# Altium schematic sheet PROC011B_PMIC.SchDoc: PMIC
size 431 x 279 mm; Date: Not shown in title block; ApprovedBy: Not shown in title block; CheckedBy: Not shown in title block; Author: Not shown in title block; CompanyName: Not shown in title block; Engineer: Not shown in title block; Organization: Not shown in title block; Address1: Not shown in title block; Address2: Not shown in title block; Address3: Not shown in title block; Address4: Not shown in title block; DocumentNumber: 1; Revision: Use project parameter SCH_Rev; SheetNumber: 8; SheetTotal: 17; PageSetup: Record=PageOptions¦CenterHorizontal=True¦CenterVertical=True¦PrintScale=1.00¦XCorrection=1.00¦YCorrection=1.00¦PrintKind=0¦BorderSize=5000000¦LeftOffset=0¦BottomOffset=0¦Orientation=2¦PaperLength=1000¦PaperWidth=1000¦Scale=100¦PaperSource=15¦PrintQuality=600¦MediaType=1¦DitherType=10¦PaperKind=Letter¦PrintScaleMode=1
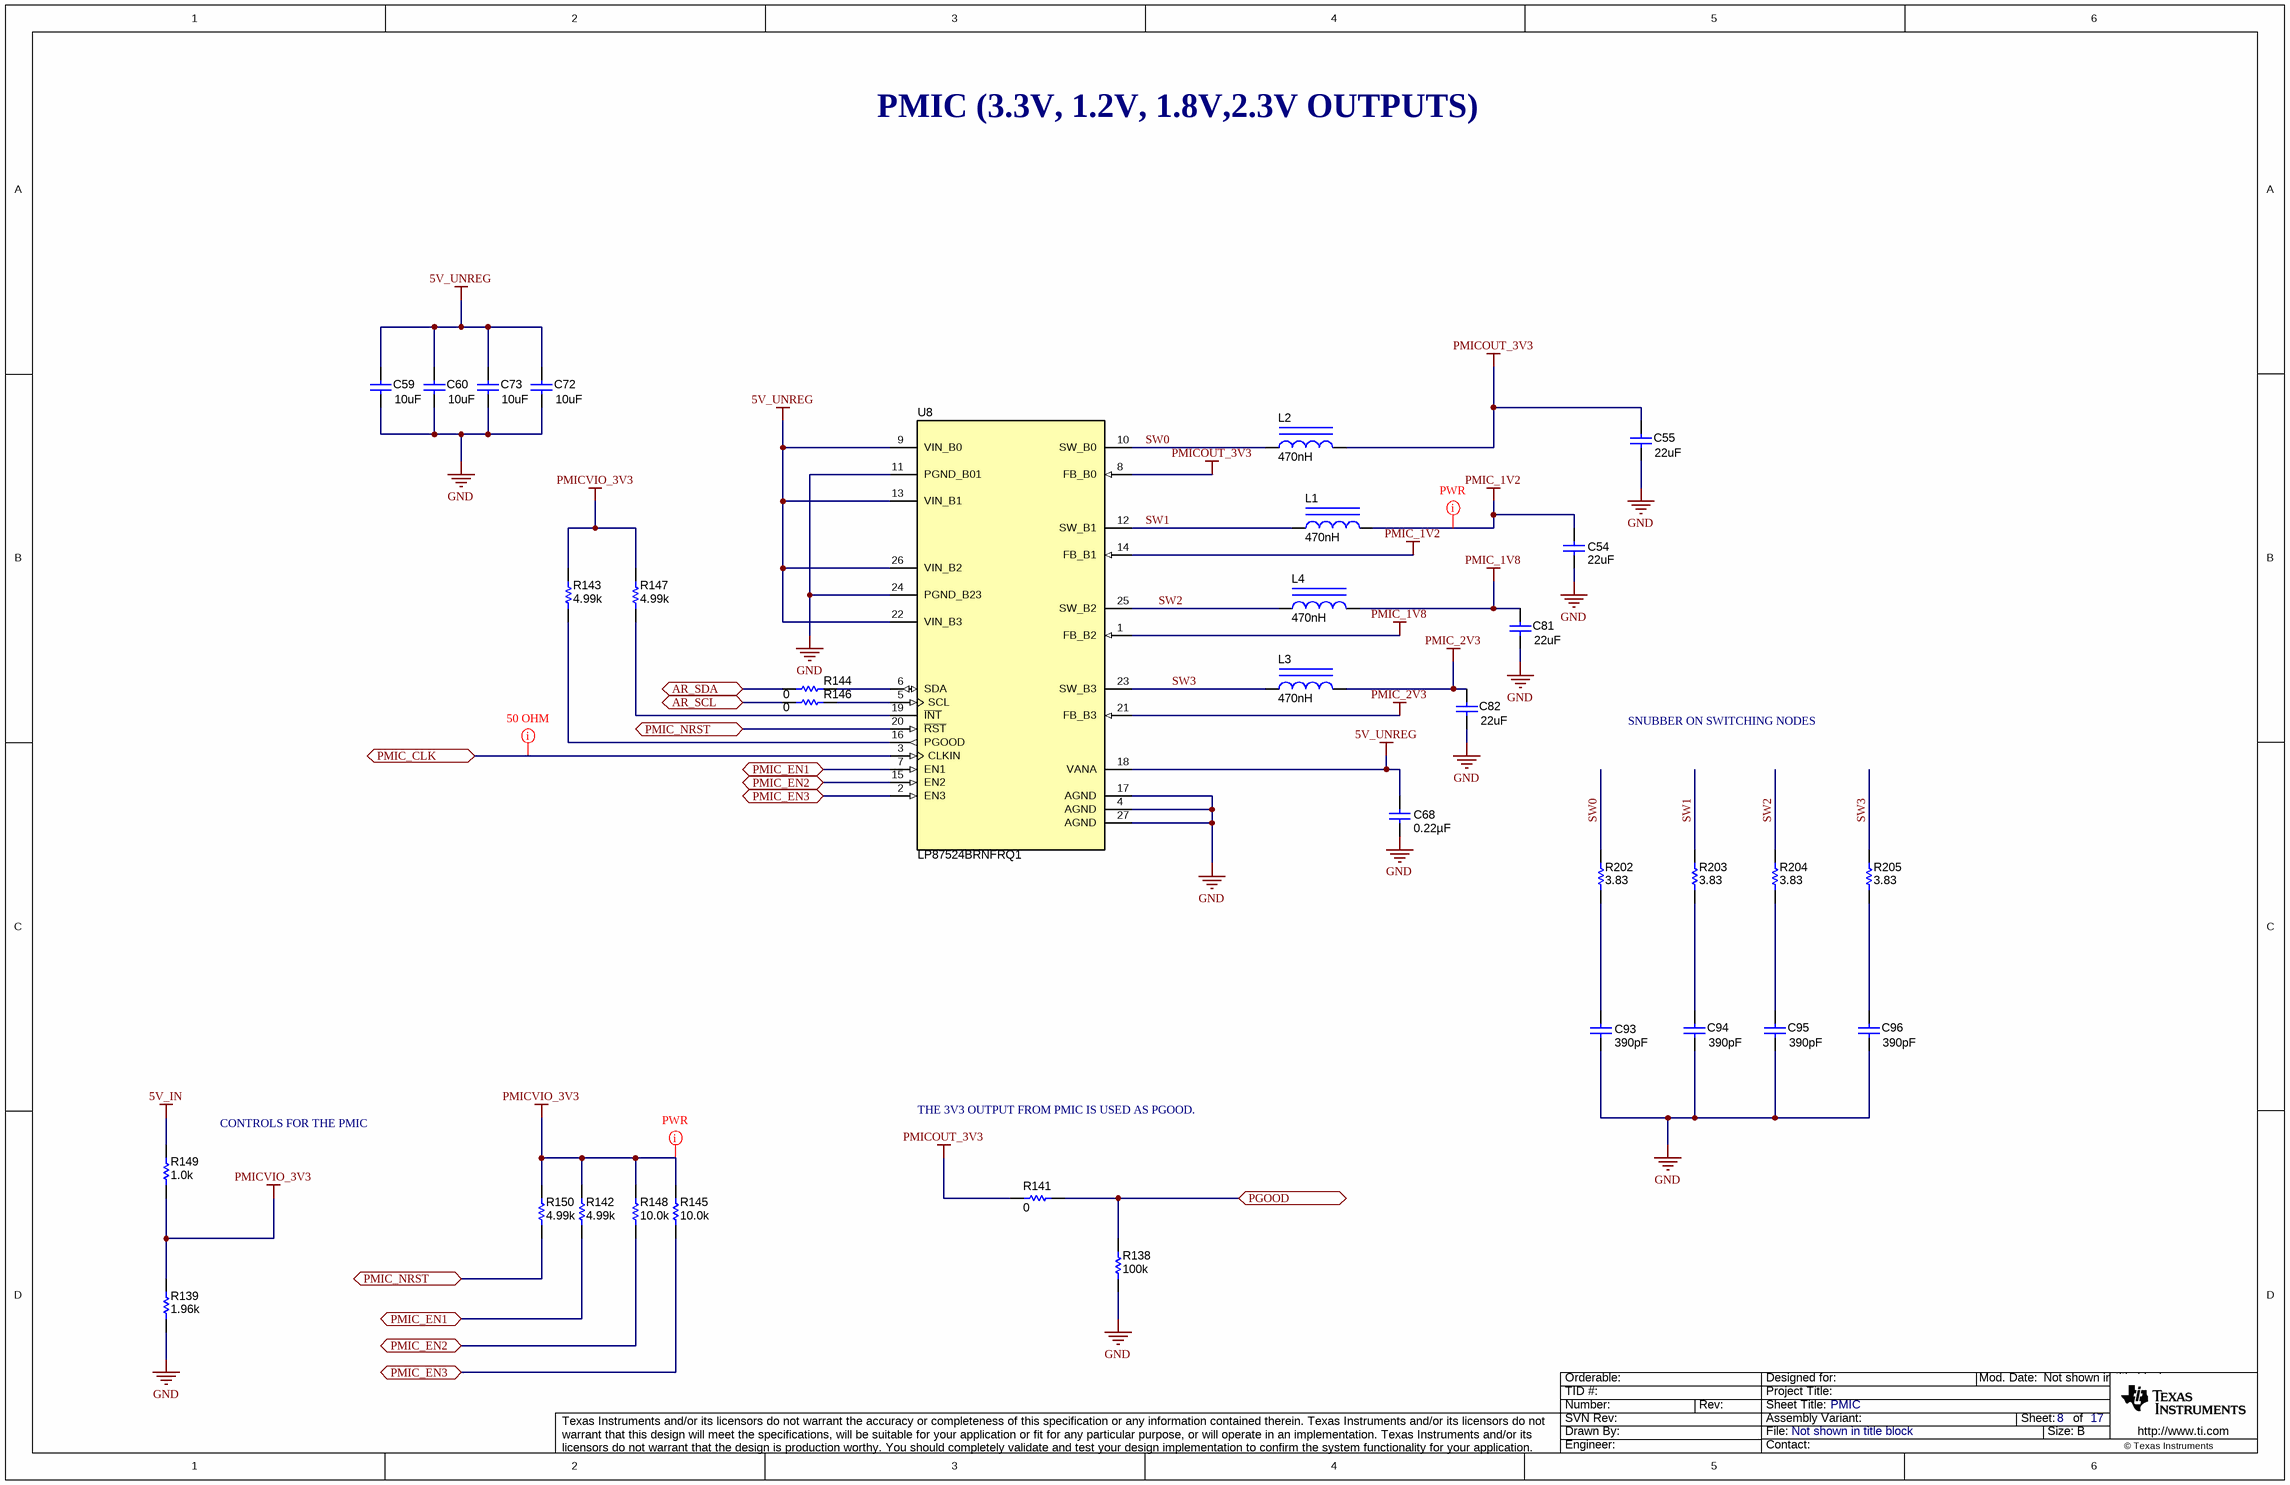
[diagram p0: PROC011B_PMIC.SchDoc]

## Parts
C54  ValueDisplayed: 22uF  [1206_180]  (hidden comment: GCM31CR71A226KE02)
C55  ValueDisplayed: 22uF  [1206_180]  (hidden comment: GCM31CR71A226KE02)
C59  ValueDisplayed: 10uF  [0805_HV]  (hidden comment: GCM21BR71A106KE22L)
C60  ValueDisplayed: 10uF  [0805_HV]  (hidden comment: GCM21BR71A106KE22L)
C68  ValueDisplayed: 0.22µF  [0402L]  (hidden comment: GCM155R71C224KE02D)
C72  ValueDisplayed: 10uF  [0805_HV]  (hidden comment: GCM21BR71A106KE22L)
C73  ValueDisplayed: 10uF  [0805_HV]  (hidden comment: GCM21BR71A106KE22L)
C81  ValueDisplayed: 22uF  [1206_180]  (hidden comment: GCM31CR71A226KE02)
C82  ValueDisplayed: 22uF  [1206_180]  (hidden comment: GCM31CR71A226KE02)
C93  ValueDisplayed: 390pF  [0402L]  (hidden comment: CGA2B2NP01H391J050BA)
C94  ValueDisplayed: 390pF  [0402L]  (hidden comment: CGA2B2NP01H391J050BA)
C95  ValueDisplayed: 390pF  [0402L]  (hidden comment: CGA2B2NP01H391J050BA)
C96  ValueDisplayed: 390pF  [0402L]  (hidden comment: CGA2B2NP01H391J050BA)
L1  ValueDisplayed: 470nH  [DFE252012P]  (hidden comment: DFE252012P-R47M=P2)
L2  ValueDisplayed: 470nH  [DFE252012P]  (hidden comment: DFE252012P-R47M=P2)
L3  ValueDisplayed: 470nH  [DFE252012P]  (hidden comment: DFE252012P-R47M=P2)
L4  ValueDisplayed: 470nH  [DFE252012P]  (hidden comment: DFE252012P-R47M=P2)
R138  ValueDisplayed: 100k  [0402L]  (hidden comment: CRCW0402100KFKED)
R139  ValueDisplayed: 1.96k  [0402L]  (hidden comment: CRCW04021K96FKED)
R141  ValueDisplayed: 0  [0402L]  (hidden comment: ERJ-2GE0R00X)
R142  ValueDisplayed: 4.99k  [0402L]  (hidden comment: ERJ-2RKF4991X)
R143  ValueDisplayed: 4.99k  [0402L]  (hidden comment: CRCW04024K99FKED)
R144  ValueDisplayed: 0  [0201_Silk]  (hidden comment: CRCW02010000Z0ED)
R145  ValueDisplayed: 10.0k  [0402L]  (hidden comment: CRCW040210K0FKED)
R146  ValueDisplayed: 0  [0201_Silk]  (hidden comment: CRCW02010000Z0ED)
R147  ValueDisplayed: 4.99k  [0402L]  (hidden comment: CRCW04024K99FKED)
R148  ValueDisplayed: 10.0k  [0402L]  (hidden comment: CRCW040210K0FKED)
R149  ValueDisplayed: 1.0k  [0402L]  (hidden comment: ERJ-2GEJ102X)
R150  ValueDisplayed: 4.99k  [0402L]  (hidden comment: ERJ-2RKF4991X)
R202  ValueDisplayed: 3.83  [0402L]  (hidden comment: CRCW04023R83FKED)
R203  ValueDisplayed: 3.83  [0402L]  (hidden comment: CRCW04023R83FKED)
R204  ValueDisplayed: 3.83  [0402L]  (hidden comment: CRCW04023R83FKED)
R205  ValueDisplayed: 3.83  [0402L]  (hidden comment: CRCW04023R83FKED)
U8  LP87524BRNFRQ1  [RNF0026C]

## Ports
AR_SCL, AR_SDA, PGOOD, PMIC_CLK, PMIC_EN1, PMIC_EN2, PMIC_EN3, PMIC_NRST

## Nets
5V_IN: R149.2
5V_UNREG: C59.2 C60.2 C68.2 C72.2 C73.2 U8.9(VIN_B0) U8.13(VIN_B1) U8.18(VANA) U8.22(VIN_B3) U8.26(VIN_B2)
GND: C54.1 C55.1 C59.1 C60.1 C68.1 C72.1 C73.1 C81.1 C82.1 C93.1 C94.1 C95.1 C96.1 R138.1 R139.1 U8.4(AGND) U8.11(PGND_B01) U8.17(AGND) U8.24(PGND_B23) U8.27(AGND)
PMIC_1V2: C54.2 L1.2 U8.14(FB_B1)
PMIC_1V8: C81.2 L4.2 U8.1(FB_B2)
PMIC_2V3: C82.2 L3.2 U8.21(FB_B3)
PMICOUT_3V3: C55.2 L2.2 R141.1 U8.8(FB_B0)
PMICVIO_3V3: R139.2 R142.2 R143.2 R145.2 R147.2 R148.2 R149.1 R150.1
AR_SCL: R146.1 ; port AR_SCL
AR_SDA: R144.2 ; port AR_SDA
PGOOD: R138.2 R141.2 ; port PGOOD
PMIC_CLK: U8.3(CLKIN) ; port PMIC_CLK
PMIC_EN1: R142.1 U8.7(EN1) ; port PMIC_EN1
PMIC_EN2: R148.1 U8.15(EN2) ; port PMIC_EN2
PMIC_EN3: R145.1 U8.2(EN3) ; port PMIC_EN3
PMIC_NRST: R150.2 U8.20(~{RST}) ; port PMIC_NRST
SW0: L2.1 R202.2 U8.10(SW_B0)
SW1: L1.1 R203.2 U8.12(SW_B1)
SW2: L4.1 R204.2 U8.25(SW_B2)
SW3: L3.1 R205.2 U8.23(SW_B3)
NetC93_2: C93.2 R202.1
NetC94_2: C94.2 R203.1
NetC95_2: C95.2 R204.1
NetC96_2: C96.2 R205.1
NetR143_1: R143.1 U8.16(PGOOD)
NetR144_1: R144.1 U8.6(SDA)
NetR146_2: R146.2 U8.5(SCL)
NetR147_1: R147.1 U8.19(~{INT})

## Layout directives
net class 50_OHM: PMIC_CLK
net class PWR: PMIC_1V2, PMICVIO_3V3

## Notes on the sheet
- PMIC (3.3V, 1.2V, 1.8V,2.3V OUTPUTS)
- SNUBBER ON SWITCHING NODES
- CONTROLS FOR THE PMIC
- THE 3V3 OUTPUT FROM PMIC IS USED AS PGOOD.

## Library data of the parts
C54 = CMP-0008811-2: CAP, CERM, 22 uF, 10 V, +/- 10%, X7R, AEC-Q200 Grade 1, 1206; Manufacturer: MuRata; TaMin_C: -55°C; Polarized: N; SizeAreaWB_mm2: 10.92; Value1: Unknown; U/M: EA; Value: 22uF; TaMax_C: 125°C; SizeZ_mm: 1.8; SizeX_mm: 3.2; SizeY_mm: 1.6; Cap_Case: 1206; Value2: 10V; SizeArea_mm2: 5.12; CompType: Capacitor; AEC Qualified: Y; Cap_F: 22µF; AEC Grade: 1; AEC Category: Q200
C55 C81 C82 = CMP-0008811-2: CAP, CERM, 22 uF, 10 V, +/- 10%, X7R, AEC-Q200 Grade 1, 1206; Manufacturer: MuRata; TaMin_C: -55°C; Polarized: N; SizeAreaWB_mm2: 10.92; Value1: Unknown; U/M: EA; Value: 22uF; TaMax_C: 125°C; SizeZ_mm: 1.8; SizeX_mm: 3.2; SizeY_mm: 1.6; Cap_Case: 1206; Value2: 10V; SizeArea_mm2: 5.12; AEC Qualified: Y; Cap_F: 22µF; AEC Grade: 1; AEC Category: Q200
C59 C60 C72 C73 = CMP-0008017-2: CAP, CERM, 10 uF, 10 V, +/- 10%, X7R, 0805; Manufacturer: MuRata; TaMin_C: -55°C; Polarized: N; SizeAreaWB_mm2: 6.75; Value1: Unknown; U/M: EA; Value: 10uF; TaMax_C: 125°C; SizeZ_mm: 1.45; SizeX_mm: 2; SizeY_mm: 1.25; Cap_Case: 0805; Value2: 10V; SizeArea_mm2: 2.5; CompType: Capacitor; Cap_F: 10µF; AEC Category: Q200
C68 = CMP-0078265-1: CAP, CERM, 0.22 µF, 16 V,+/- 10%, X7R, AEC-Q200 Grade 1, 0402; Manufacturer: MuRata; TaMin_C: -55°C; Polarized: N; SizeAreaWB_mm2: 3; U/M: EA; Value: 0.22uF; TaMax_C: 125°C; SizeZ_mm: 0.6; SizeX_mm: 1; SizeY_mm: 0.5; Cap_Case: 0402; Value2: 16V; CompType: Capacitor; AEC Qualified: Y; Cap_F: 220nF; AEC Category: Q200
C93-C96 = CMP-0078223-1: CAP, CERM, 390 pF, 50 V,+/- 5%, C0G/NP0, AEC-Q200 Grade 0, 0402; Manufacturer: TDK; TaMin_C: -55°C; Polarized: N; SizeAreaWB_mm2: 3; U/M: EA; Value: 390pF; TaMax_C: 150°C; SizeZ_mm: 0.6; SizeX_mm: 1; SizeY_mm: 0.5; Cap_Case: 0402; Value2: 50V; AEC Qualified: Y; AEC Grade: 0; AEC Category: Q200
L1-L4 = CMP-0058946-1: Inductor, Shielded, 470 nH, 4.7 A, 0.021 ohm, SMD; Manufacturer: MuRata Toko; Isat: 6.4A @ 30% inductance drop; Irms: 4.7A @ 40C rise; SizeAreaWB_mm2: 10.5; DCR_ohm: 0.021; Value: 470nH; Imax_A: 4.7A; SizeZ_mm: 1.2; SizeX_mm: 2.5; SizeY_mm: 2; SizeArea_mm2: 5; AEC Category: Q200
R138 = CMP-0025950-2: RES, 100 k, 1%, 0.063 W, 0402; Manufacturer: Vishay-Dale; Power_W: 63mW; TempCo: 100 ppm/C; U/M: EA; Value: 100k; EIA_Code: E96; SizeX_mm: 1; SizeY_mm: 0.5; SizeZ_mm: 0.6; Value2: 0.063W; VDC_V: 50V; AEC Category: Q200
R139 = CMP-0026099-1: RES, 1.96 k, 1%, 0.063 W, 0402; Manufacturer: Vishay-Dale; Power_W: 63mW; TempCo: 100 ppm/C; Value_Code: 1k96; U/M: EA; Value: 1.96k; EIA_Code: E96; SizeX_mm: 1; SizeY_mm: 0.5; SizeZ_mm: 0.6; Value2: 0.063W; CompType: Resistor; VDC_V: 50V; AEC Category: Q200
R141 = CMP-0026992-2: RES, 0, 5%, 0.063 W, 0402; Manufacturer: Panasonic; Power_W: 63mW; TempCo: 600 ppm/C; Value_Code: 0000; U/M: EA; Value: 0; EIA_Code: E24; SizeX_mm: 1; SizeY_mm: 0.5; SizeZ_mm: 0.6; Value2: 0.063W; VDC_V: 50V; AEC Category: Q200
R142 R150 = CMP-0026701-1: RES, 4.99 k, 1%, 0.1 W, AEC-Q200 Grade 0, 0402; Manufacturer: Panasonic; Power_W: 100mW; TempCo: 100 ppm/C; Value_Code: 4k99; U/M: EA; Value: 4.99k; EIA_Code: E96; SizeX_mm: 1; SizeY_mm: 0.5; SizeZ_mm: 0.6; Value2: 0.1W; AEC Qualified: Y; VDC_V: 50V; AEC Grade: 0; AEC Category: Q200
R143 R147 = CMP-0026414-1: RES, 4.99 k, 1%, 0.063 W, 0402; Manufacturer: Vishay-Dale; Power_W: 63mW; TempCo: 100 ppm/C; Value_Code: 4k99; U/M: EA; Value: 4.99k; EIA_Code: E96; SizeX_mm: 1; SizeY_mm: 0.5; SizeZ_mm: 0.6; Value2: 0.063W; VDC_V: 50V; AEC Category: Q200
R144 R146 = CMP-0027008-3: RES, 0, 5%, 0.05 W, 0201; Manufacturer: Vishay-Dale; Power_W: 50mW; TempCo: ppm/C; Value_Code: 0000; U/M: EA; Value: 0; EIA_Code: E24; SizeX_mm: 0.6; SizeY_mm: 0.3; SizeZ_mm: 0.26; Value2: 0.05W; SizeArea_mm2: 0.18; AEC Qualified: N; AEC Category: Q200
R145 R148 = CMP-0025958-2: RES, 10.0 k, 1%, 0.063 W, 0402; Manufacturer: Vishay-Dale; Power_W: 63mW; TempCo: 100 ppm/C; Value_Code: 10k0; U/M: EA; Value: 10.0k; EIA_Code: E96; Res_ohm: 10k; SizeX_mm: 1; SizeY_mm: 0.5; SizeZ_mm: 0.6; Value2: 0.063W; VDC_V: 50V; AEC Category: Q200
R149 = CMP-0078193-1: RES, 1.0 k, 5%, 0.1 W, AEC-Q200 Grade 0, 0402; Manufacturer: Panasonic; Value_Code: 1k00; SizeArea_mm2: 0.5; AEC Qualified: Y; AEC Category: Q200; Res_ohm: 1k; Value: 1.0k; SizeZ_mm: 0.6; Green_REACh: Passed; EIA_Code: E24; TempCo: 200 ppm/C; AEC Grade: 0; Power_W: 100mW; VDC_V: 50V; Value2: 0.1W; Green_Lifecycle: Active; U/M: EA; SizeX_mm: 1
R202-R205 = CMP-0026363-1: RES, 3.83, 1%, 0.063 W, 0402; Manufacturer: Vishay-Dale; Power_W: 63mW; TempCo: 100 ppm/C; Value_Code: 3R83; U/M: EA; Value: 3.83; EIA_Code: E96; SizeX_mm: 1; SizeY_mm: 0.5; SizeZ_mm: 0.6; Value2: 0.063W; VDC_V: 50V; AEC Category: Q200
U8 = CMP-0013883-2: Four-Phase 2.5-A-per-Phase Buck Converter With Integrated Switches, RNF0026C (VQFN-HR-26); Manufacturer: Texas Instruments; SizeX_mm: 4; SizeY_mm: 4.5; CompType: IC; SizeZ_mm: 0.9; SizeArea_mm2: 18; SizeAreaWB_mm2: 27.5; U/M: EA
